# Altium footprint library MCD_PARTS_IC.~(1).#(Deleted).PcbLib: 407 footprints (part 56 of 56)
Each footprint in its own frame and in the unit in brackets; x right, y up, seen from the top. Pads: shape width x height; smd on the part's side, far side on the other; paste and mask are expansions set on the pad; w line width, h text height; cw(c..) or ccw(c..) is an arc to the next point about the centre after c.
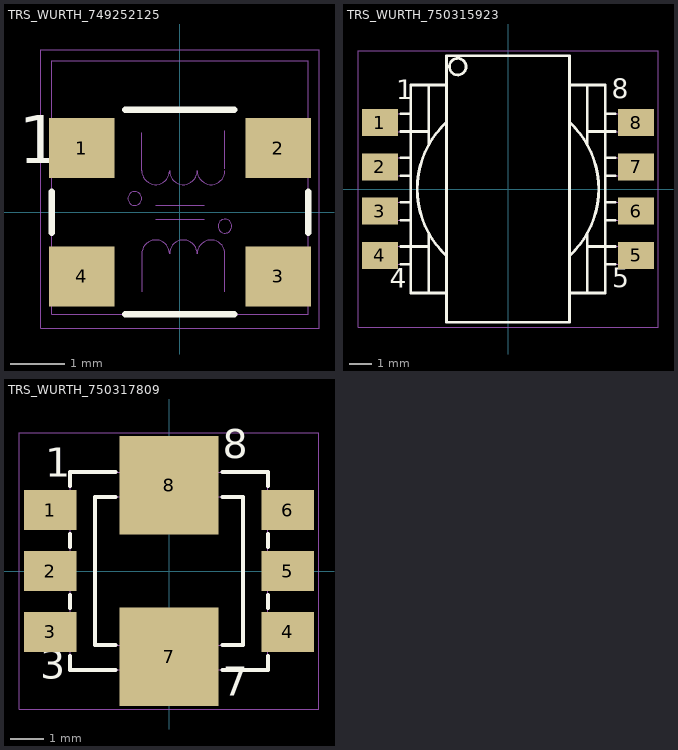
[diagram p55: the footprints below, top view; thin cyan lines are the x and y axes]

## TRS_WURTH_749252125 [mm] "MCD-04314"
height 3.55
pads (4):
  rect 1.2x1.1 smd mask+0.05: 1(-1.8,1.175) 2(1.8,1.175) 3(1.8,-1.175) 4(-1.8,-1.175)
Top Overlay:
  lines w0.12: -2.35,-0.375 -2.35,0.375 ; -1,-1.875 1,-1.875 ; -1,1.875 1,1.875 ; 2.35,-0.375 2.35,0.375
  text "1" at -2.95,0.6 h1.5
M14-Top Assembly:
  circle w0.01: c-0.826,0.252 r0.127
  circle w0.01: c0.826,-0.256 r0.127
  lines w0.01: -0.698,-1.462 -0.699,-0.764 cw(c-0.445,-0.764) -0.191,-0.764 cw(c0.064,-0.764) 0.318,-0.764 cw(c0.572,-0.764) 0.826,-0.764 0.826,-1.462 ; -0.698,1.459 -0.699,0.76 ccw(c-0.445,0.76) -0.191,0.76 ccw(c0.064,0.76) 0.318,0.76 ccw(c0.572,0.76) 0.826,0.76 ; -0.445,-0.129 0.445,-0.129 ; -0.445,0.125 0.445,0.125 ; 0.826,0.792 0.826,1.49 ; -2.35,-1.875 -2.35,2.775 2.35,2.775 2.35,-1.875 -2.35,-1.875
  text "3" at 1.55,-1.633 h1.5
  text "2" at 1.524,0.7 h1.5
  text "1" at -2.075,0.675 h1.5
  text "4" at -2.1,-1.65 h1.5
  text "'.Designator'" at 0,0 h0.75
  text "P" at 0.375,-1.4 h1
  text "S" at 0.388,0.9 h1
M16-Top Courtyard:
  lines w0.01: -2.55,-2.125 -2.55,2.975 2.55,2.975 2.55,-2.125 -2.35,-2.125 -2.55,-2.125
3D body "749252125.stp": height 3.26, standoff 0, extent -2.1,-1.6 2.1,2.1

## TRS_WURTH_750315923 [mm]
height 6.1
pads (8):
  rect 1.63x1.22 smd mask+0.05: 1(-5.79,3) 2(-5.79,1) 3(-5.79,-1) 4(-5.79,-3) 5(5.79,-3) 6(5.79,-1) 7(5.79,1) 8(5.79,3)
Top Overlay:
  circle w0.12: c-2.27,5.525 r0.375
  lines w0.12: -4.85,-3.405 -4.395,-3.405 ; -4.85,-2.595 -3.585,-2.595 ; -4.85,-1.405 -4.395,-1.405 ; -4.85,-0.595 -4.395,-0.595 ; -4.85,0.595 -4.395,0.595 ; -4.85,1.405 -4.395,1.405 ; -4.85,2.595 -3.585,2.595 ; -4.85,3.405 -4.395,3.405 ; -3.585,-1.99 -3.585,-4.7 ; -3.585,1.99 -3.585,4.7 ; -2.777,-3.017 cw(c0,0) -2.777,3.017 ; -2.775,-3.405 -2.775,-4.7 -3.585,-4.7 ; 2.775,-4.7 3.585,-4.7 ; 2.775,4.7 3.585,4.7 ; 2.777,-3.017 ccw(c0,0) 2.777,3.017 ; 3.585,-2.595 4.85,-2.595 ; 3.585,-1.99 3.585,-4.7 ; 3.585,1.99 3.585,4.7 ; 3.585,2.595 4.85,2.595 ; 4.395,-1.405 4.85,-1.405 ; 4.395,-0.595 4.85,-0.595 ; 4.395,0.595 4.85,0.595 ; 4.395,1.405 4.85,1.405 ; 4.85,-3.405 4.395,-3.405 ; 4.85,3.405 4.395,3.405 ; -4.395,-3.405 -4.395,-4.7 -3.585,-4.7 ; -4.395,-3.405 -4.395,3.405 ; -4.395,3.405 -4.395,4.7 -3.585,4.7 ; -3.585,4.7 -2.775,4.7 ; -2.775,4.7 -2.775,6.02 2.775,6.02 2.775,5.86 2.775,-6.02 -2.775,-6.02 -2.775,4.7 ; 3.585,-4.7 4.395,-4.7 4.395,-3.405 ; 3.585,4.7 4.395,4.7 4.395,3.405 ; 4.395,-3.405 4.395,3.405
  text "1" at -5.05,3.75 h1.5
  text "4" at -5.35,-4.75 h1.5
  text "5" at 4.7,-4.725 h1.5
  text "8" at 4.675,3.8 h1.5
M14-Top Assembly:
  circle w0.01: c-2.27,5.525 r0.375
  lines w0.01: -4.395,-1.405 -5.41,-1.405 ; -4.395,-0.595 -5.41,-0.595 ; -4.395,0.595 -5.41,0.595 ; -4.395,1.405 -5.41,1.405 ; -3.585,-2.595 -5.41,-2.595 ; -3.585,-1.99 -3.585,-4.7 ; -3.585,1.99 -3.585,4.7 ; -3.585,2.595 -5.41,2.595 ; -2.777,-3.017 cw(c0,0) -2.777,3.017 ; -2.775,-3.405 -2.775,-4.7 -3.585,-4.7 ; 2.775,-4.7 3.585,-4.7 ; 2.775,4.7 3.585,4.7 ; 2.777,-3.017 ccw(c0,0) 2.777,3.017 ; 3.585,-2.595 5.41,-2.595 ; 3.585,-1.99 3.585,-4.7 ; 3.585,1.99 3.585,4.7 ; 3.585,2.595 5.41,2.595 ; 4.395,-1.405 5.41,-1.405 ; 4.395,-0.595 5.41,-0.595 ; 4.395,0.595 5.41,0.595 ; 4.395,1.405 5.41,1.405 ; -5.41,-3.405 -5.41,-2.595 ; -5.41,-3.405 -4.395,-3.405 ; -5.41,-3.405 -6.425,-3.405 -6.425,-2.595 -5.41,-2.595 ; -5.41,-1.405 -5.41,-0.595 ; -5.41,-1.405 -6.425,-1.405 -6.425,-0.595 -5.41,-0.595 ; -5.41,0.595 -5.41,1.405 ; -5.41,0.595 -6.425,0.595 -6.425,1.405 -5.41,1.405 ; -5.41,2.595 -5.41,3.405 ; -5.41,2.595 -6.425,2.595 -6.425,3.405 -5.41,3.405 ; -5.41,3.405 -4.395,3.405 ; -4.395,-3.405 -4.395,3.405 ; -4.395,-3.405 -4.395,-4.7 -3.585,-4.7 ; -4.395,3.405 -4.395,4.7 -3.585,4.7 ; -3.585,4.7 -2.775,4.7 ; -2.775,4.7 -2.775,-6.02 2.775,-6.02 2.775,5.86 2.775,6.02 -2.775,6.02 -2.775,4.7 ; 3.585,-4.7 4.395,-4.7 4.395,-3.405 ; 3.585,4.7 4.395,4.7 4.395,3.405 ; 4.395,-3.405 5.41,-3.405 ; 4.395,-3.405 4.395,3.405 ; 4.395,3.405 5.41,3.405 ; 5.41,-3.405 5.41,-2.595 ; 5.41,-3.405 6.425,-3.405 6.425,-2.595 5.41,-2.595 ; 5.41,-1.405 5.41,-0.595 ; 5.41,-1.405 6.425,-1.405 6.425,-0.595 5.41,-0.595 ; 5.41,0.595 5.41,1.405 ; 5.41,0.595 6.425,0.595 6.425,1.405 5.41,1.405 ; 5.41,2.595 5.41,3.405 ; 5.41,2.595 6.425,2.595 6.425,3.405 5.41,3.405
  text "1" at -6.095,2.64 h1.1
  text "2" at -6.155,0.64 h1.1
  text "3" at -6.15,-1.35 h1.1
  text "4" at -6.175,-3.355 h1.1
  text "5" at 5.715,-3.345 h1.1
  text "6" at 5.7,-1.35 h1.1
  text "7" at 5.71,0.645 h1.1
  text "8" at 5.71,2.645 h1.1
  text "'.Designator'" at -2,-0.5 h0.75
M16-Top Courtyard:
  lines w0.01: -6.775,-6.25 -6.775,3.475 -6.775,6.25 3.675,6.25 6.775,6.25 6.775,3.2 6.775,-6.25 -6.775,-6.25
3D body: height 6.11, standoff 6.1, extent -2.578,5.226 -1.98,5.825
3D body: height 6.1, standoff 0, extent -2.775,-6.02 2.775,6.02
3D body: height 1, standoff 0.5, extent 4.395,-3.405 6.425,-2.595
3D body: height 0.5, standoff 0, extent 5.41,-3.405 6.425,-2.595
3D body: height 1, standoff 0.5, extent 4.395,-1.405 6.425,-0.595
3D body: height 0.5, standoff 0, extent 5.41,-1.405 6.425,-0.595
3D body: height 1, standoff 0.5, extent 4.395,0.595 6.425,1.405
3D body: height 0.5, standoff 0, extent 5.41,0.595 6.425,1.405
3D body: height 1, standoff 0.5, extent 4.395,2.595 6.425,3.405
3D body: height 0.5, standoff 0, extent 5.41,2.595 6.425,3.405
3D body: height 1, standoff 0.5, extent -6.425,-3.405 -4.395,-2.595
3D body: height 0.5, standoff 0, extent -6.425,-3.405 -5.41,-2.595
3D body: height 1, standoff 0.5, extent -6.425,-1.405 -4.395,-0.595
3D body: height 0.5, standoff 0, extent -6.425,-1.405 -5.41,-0.595
3D body: height 1, standoff 0.5, extent -6.425,0.595 -4.395,1.405
3D body: height 0.5, standoff 0, extent -6.425,0.595 -5.41,1.405
3D body: height 0.5, standoff 0, extent -6.425,2.595 -5.41,3.405
3D body: height 1, standoff 0.5, extent -6.425,2.595 -4.395,3.405
3D body: height 2, standoff 0, extent -4.395,-4.7 -2.775,4.7
3D body: height 2, standoff 0, extent 2.775,-4.7 4.395,4.7
3D body: height 5, standoff 2, extent -4.099,-3.017 -2.774,3.015
3D body: height 5, standoff 2, extent 2.774,-3.015 4.099,3.017

## TRS_WURTH_750317809 [mm] "MCD-01596"
height 5.5
pads (8):
  rect 1.6x1.2 smd mask+0.05: 1(-3.6,1.85) 2(-3.6,0) 3(-3.6,-1.85) 4(3.6,-1.85) 5(3.6,0) 6(3.6,1.85)
  rect 3x3 smd mask+0.05: 7(0,-2.6) 8(0,2.6)
Top Overlay:
  lines w0.12: -3,-2.575 -3,-3 -1.625,-3 ; -3,-1.125 -3,-0.725 ; -3,0.725 -3,1.125 ; -3,2.575 -3,3 -1.625,3 ; -1.625,-2.25 -2.25,-2.25 -2.25,2.25 -1.625,2.25 ; 1.625,-3 3,-3 3,-2.575 ; 1.625,-2.25 2.25,-2.25 2.25,2.25 1.625,2.25 ; 1.625,3 3,3 3,2.575 ; 3,-1.125 3,-0.725 ; 3,0.725 3,1.125
  text "1" at -3.75,2.575 h1.5
  text "3" at -3.9,-3.55 h1.5
  text "8" at 1.625,3.125 h1.5
  text "7" at 1.625,-4.075 h1.5
M14-Top Assembly:
  lines w0.01: -3,-2.375 -3.9,-2.375 -3.9,-1.325 -3,-1.325 ; -3,-0.525 -3.9,-0.525 -3.9,0.525 -3,0.525 ; -3,1.325 -3.9,1.325 -3.9,2.375 -3,2.375 ; -1.425,-3 -1.425,-3.6 1.425,-3.6 1.425,-3 ; -1.425,3 -1.425,3.6 1.425,3.6 1.425,3 ; 3,-2.375 3.9,-2.375 3.9,-1.325 3,-1.325 ; 3,-0.525 3.9,-0.525 3.9,0.525 3,0.525 ; 3,1.325 3.9,1.325 3.9,2.375 3,2.375 ; -3,-3 -3,3 3,3 3,-3 -3,-3 ; -2.25,-2.25 2.25,-2.25 2.25,2.25 -2.25,2.25 -2.25,-2.25
  text "'.Designator'" at -1.99,-0.55 h0.75
  text "1" at -3.6,1.425 h1.3
  text "2" at -3.725,-0.425 h1.3
  text "3" at -3.725,-2.275 h1.3
  text "7" at -0.275,-3.55 h1.3
  text "4" at 3.15,-2.275 h1.3
  text "5" at 3.175,-0.4 h1.3
  text "6" at 3.175,1.45 h1.3
  text "8" at -0.275,2.7 h1.3
M16-Top Courtyard:
  lines w0.01: 4.55,3.7 4.55,4 ; -4.55,-4.2 4.55,-4.2 4.55,4.2 -4.55,4.2 -4.55,2.5 -4.55,-4.2
3D body: height 5.33, standoff 0, extent -3,-3 3,3
3D body "STEP-WE-CST-EE5-rev1.stp": height 5.33, standoff 0, extent -3.85,-3.45 3.85,3.45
